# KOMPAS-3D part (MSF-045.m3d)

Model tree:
1. Ось X
2. Ось Y
3. Ось Z
4. Начало координат  (labels: Операция без истории:1)

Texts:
  Линия-выноска #1
  Линия-выноска #2
  Линия-выноска #3
  Отклонения формы и база
  Марка координационной оси
  Марка/позиционное обозначение с линией-выноской
  Марка/позиционное обозначение на линии
  Марка/позиционное обозначение без линии-выноски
